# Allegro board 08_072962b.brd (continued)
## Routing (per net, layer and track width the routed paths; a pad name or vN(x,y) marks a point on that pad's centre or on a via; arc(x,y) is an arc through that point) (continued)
UNNAMED_2_ADLTM4638_I41_PGOOD: length 3.9
  TOP w0.203: U2.B5 v3(53.09,54.2)
  BOTTOM w0.203: R51.1 55.21,54.74 53.63,54.74 v3(53.09,54.2)
UNNAMED_2_ADLTM4638_I41_PHMODE: length 5.3
  TOP w0.203: U2.G5 v3(53.09,49.4)
  BOTTOM w0.203: R7.2 R12.1 55.52,48.67 55.32,48.87 53.62,48.87 v3(53.09,49.4)
UNNAMED_2_ADLTM4638_I41_RUN: length 5.8
  TOP w0.203: U2.B4 v3(52.29,54.2)
  BOTTOM w0.203: R15.2 R9.2 53.34,55.25 v3(52.29,54.2)
UNNAMED_2_ADLTM4638_I41_TRACK: length 6.2
  TOP w0.203: U2.E2 v3(50.69,51.8)
  L4_SIG w0.152: v3(50.69,51.8) 50.69,49.97 51.1,49.57 51.1,49.01 50.23,48.14 49.69,48.14 v1(49.66,48.12)
  BOTTOM w0.203: R20.1 49.63,48.14 v1(49.66,48.12)
UNNAMED_2_ADLTM4638_I41_TSENSE: length 2.2
  TOP w0.203: U2.A6 v3(53.89,54.2)
  BOTTOM w0.406: R19.2 53.89,52.75 v3(53.89,54.2)
UNNAMED_2_ADLTM4638_I61_COMPA: length 4.4
  TOP w0.203: U3.D1 v3(62.96,51.8)
  BOTTOM w0.203: R31.2 59.39,52.05 C25.2 61.66,52.05 R40.1 62.11,51.8 v3(62.96,51.8)
UNNAMED_2_ADLTM4638_I61_COMPB: length 1.9
  TOP w0.203: U3.F1 v3(62.96,51)
  BOTTOM w0.203: v3(62.96,51) 62.11,51 R40.2
UNNAMED_2_ADLTM4638_I61_FREQ: length 5.9
  TOP w0.203: U3.E1 v3(63.76,51)
  L4_SIG w0.152: v1(61.44,48.88) 61.8,49.24 61.8,49.24 62.06,49.5 62.06,49.91 62.34,50.2 62.96,50.2 v3(63.76,51)
  BOTTOM w0.203: R25.1 R24.2 v1(61.44,48.88)
UNNAMED_2_ADLTM4638_I61_PGOOD: length 3.9
  TOP w0.203: U3.B5 v3(66.96,54.2)
  BOTTOM w0.203: v3(66.96,54.2) 67.5,54.74 69.08,54.74 R52.1
UNNAMED_2_ADLTM4638_I61_PHMODE: length 5.3
  TOP w0.203: U3.G5 v3(66.96,49.4)
  BOTTOM w0.203: R28.2 R34.1 69.39,48.67 69.19,48.87 67.49,48.87 v3(66.96,49.4)
UNNAMED_2_ADLTM4638_I61_RUN: length 5.8
  TOP w0.203: U3.B4 v3(66.16,54.2)
  BOTTOM w0.203: R38.2 R30.2 67.21,55.25 v3(66.16,54.2)
UNNAMED_2_ADLTM4638_I61_TRACK: length 6.2
  TOP w0.203: U3.E2 v3(64.56,51.8)
  L4_SIG w0.152: v3(64.56,51.8) 64.56,49.97 64.97,49.57 64.97,49.01 64.1,48.14 63.55,48.14 v1(63.52,48.12)
  BOTTOM w0.203: R44.1 63.49,48.14 v1(63.52,48.12)
UNNAMED_2_ADLTM4638_I61_TSENSE: length 2.2
  TOP w0.203: U3.A6 v3(67.76,54.2)
  BOTTOM w0.406: v3(67.76,54.2) 67.76,52.75 R41.2
UNNAMED_2_ADLTM4638_I71_COMPA: length 4.4
  TOP w0.203: U4.D1 v3(76.83,51.8)
  BOTTOM w0.203: v3(76.83,51.8) 75.98,51.8 R42.1 75.53,52.05 C26.2 73.26,52.05 R33.2
UNNAMED_2_ADLTM4638_I71_COMPB: length 1.9
  TOP w0.203: U4.F1 v3(76.83,51)
  BOTTOM w0.203: v3(76.83,51) 75.98,51 R42.2
UNNAMED_2_ADLTM4638_I71_FREQ: length 5.9
  TOP w0.203: U4.E1 v3(77.63,51)
  L4_SIG w0.152: v1(75.31,48.88) 75.67,49.24 75.67,49.24 75.93,49.5 75.93,49.91 76.21,50.2 76.83,50.2 v3(77.63,51)
  BOTTOM w0.203: R27.1 R26.2 v1(75.31,48.88)
UNNAMED_2_ADLTM4638_I71_PGOOD: length 3.9
  TOP w0.203: U4.B5 v3(80.83,54.2)
  BOTTOM w0.203: R53.1 82.95,54.74 81.37,54.74 v3(80.83,54.2)
UNNAMED_2_ADLTM4638_I71_PHMODE: length 5.3
  TOP w0.203: U4.G5 v3(80.83,49.4)
  BOTTOM w0.203: v3(80.83,49.4) 81.36,48.87 83.06,48.87 83.26,48.67 R36.1 R29.2
UNNAMED_2_ADLTM4638_I71_RUN: length 5.8
  TOP w0.203: U4.B4 v3(80.03,54.2)
  BOTTOM w0.203: R39.2 R32.2 81.08,55.25 v3(80.03,54.2)
UNNAMED_2_ADLTM4638_I71_TRACK: length 6.2
  TOP w0.203: U4.E2 v3(78.43,51.8)
  L4_SIG w0.152: v1(77.4,48.12) 77.42,48.14 77.97,48.14 78.84,49.01 78.84,49.57 78.43,49.97 v3(78.43,51.8)
  BOTTOM w0.203: R45.1 77.37,48.14 v1(77.4,48.12)
UNNAMED_2_ADLTM4638_I71_TSENSE: length 2.2
  TOP w0.203: U4.A6 v3(81.63,54.2)
  BOTTOM w0.406: R43.2 81.63,52.75 v3(81.63,54.2)
UNNAMED_2_CAP_I324_N2: length 1.1
  BOTTOM w0.203: R3.1 31.62,49.67 C2.2
UNNAMED_3_ADLTC6902_I54_SET: length 1.5
  TOP w0.203: R59.2 U6.10
UNNAMED_3_CAP_I44_N1: length 5.6
  BOTTOM w1.219: 34.8,19.38 34.8,21.11 C47.1 ; 34.8,19.38 L2.1 ; 34.8,19.38 L1.2
UNNAMED_3_CN3P_I18_N1: length 2.4
  BOTTOM w0.203: R48.2 P5.1
UNNAMED_3_LINLT3088_I55_OUT1: length 1.3
  TOP w0.203: U5.2 R60.1
UNNAMED_3_LINLT3088_I55_SET: length 1.3
  TOP w0.203: R58.1 U5.4
V+: length 76.7
  TOP w0.203: R65.1 v2(64.7,30.67) ; R59.1 v1(58.16,29.87) ; R61.1 v2(64.7,31.87) ; R63.1 v1(55.57,29.12)
  TOP w0.406: v1(58.9,27.62) 58.33,27.62 R60.2
  L4_SIG w0.457: v2(64.7,31.87) 67.34,31.87 71,28.22 116.69,28.22 117.29,27.62 TP29.1 ; v1(58.9,27.62) 56.1,27.62 55.57,28.16 v1(55.57,29.12) 56.31,29.87 v1(58.16,29.87) 63.9,29.87 v2(64.7,30.67)
  L4_SIG w0.508: v2(64.7,31.87) v2(64.7,30.67)
VOSNS+: length 63.3
  TOP w0.203: U1.B1 v3(35.22,54.2)
  L3_SIG w0.152: v3(35.22,54.2) 32.6,54.2 31.3,55.49 31.3,71.37 49.06,89.12 56.47,89.12 v1(57.43,90.09) 57.43,92 54.13,95.3 TP12.1
  BOTTOM w0.203: R46.1 v1(57.43,90.09)
VOSNS-: length 111
  TOP w0.203: U2.C2 v3(49.89,53.4) ; U1.C2 v3(36.03,53.4) ; U3.C2 v3(63.76,53.4) ; U4.C2 v3(77.63,53.4)
  L3_SIG w0.152: v3(49.89,53.4) 49.89,55.8 ; 49.89,55.8 37.15,55.8 36.03,54.68 ; 49.89,55.8 63.76,55.8 ; 36.03,54.68 v3(36.03,53.4) ; 36.03,54.68 32.84,54.68 v1(31.94,55.58) 31.81,55.71 31.81,71.37 49.21,88.77 58.93,88.77 v2(60.23,90.06) ; v3(63.76,53.4) 63.76,55.8 ; 63.76,55.8 75.91,55.8 77.63,54.08 v3(77.63,53.4)
  BOTTOM w0.203: R47.1 v2(60.23,90.06) ; C23.2 32.72,55.53 R22.2 v1(31.94,55.58)
VOUT: length 144.4
  TOP w0.203: TP13.1 55.38,91.69 ; TP13.1 54.13,90.44 ; TP13.1 52.89,91.69 ; TP13.1 54.13,92.93
  TOP w0.406: U4.F3 U4.G3 v3(78.43,49.4) ; v3(64.56,49.4) U3.G3 U3.F3 ; v3(50.69,49.4) U2.G3 U2.F3 ; U1.G3 v3(36.82,49.4)
  L4_SIG w0.152: v1(32.67,58.85) 32.67,71.18 51.26,89.76 55.24,89.76 57.43,91.95 v1(57.43,94.11) ; v1(58.13,96.09) 58.64,95.58 61.34,95.58 61.5,95.43 61.5,92.71 65.69,88.52 101.07,88.52 106.91,94.36 J3.1
  L5_PWR w0.203: 54.13,90.44 TP13.1 ; TP13.1 54.13,92.93 ; TP13.1 52.89,91.69 ; TP13.1 55.38,91.69
  BOTTOM w0.203: 54.13,90.44 TP13.1 ; TP13.1 54.13,92.93 ; TP13.1 55.38,91.69 ; TP13.1 52.89,91.69 ; v1(57.43,94.11) 57.43,95.36 ; v1(57.43,94.11) R46.2 ; v1(57.43,94.11) 58.49,94.11 ; v1(57.43,94.11) 56.38,94.11 ; R46.2 58.13,92.32 ; R46.2 57.43,91.76 ; R46.2 56.73,92.32 ; 57.49,96.09 v1(58.13,96.09) ; v1(58.13,96.09) 58.13,96.79 ; v1(58.13,96.09) 58.77,96.09 ; v1(58.13,96.09) 58.13,95.39
  BOTTOM w0.457: C77.1 J3.1 ; J3.1 C78.1 ; J3.1 C57.1 ; C22.1 32.67,56.83 R67.1 v1(32.67,58.85)
  vias: v1(36.6,64.68) v1(36.6,64.02) v1(36.6,63.36) v1(36.6,61.92) v1(36.6,61.26) v1(36.6,60.6) v1(36.6,59.15) v1(36.6,58.49) v1(36.6,57.83) v1(37.26,57.05) v1(37.26,56.6) v1(50.47,64.68) v1(50.47,64.02) v1(50.47,63.36) v1(50.47,61.92) v1(50.47,61.26) v1(50.47,60.6) v1(50.47,59.15) v1(50.47,58.49) v1(50.47,57.83) v1(51.13,57.05) v1(51.13,56.6) v1(64.34,64.68) v1(64.34,64.02) v1(64.34,63.36) v1(64.34,61.92) v1(64.34,61.26) v1(64.34,60.6) v1(64.34,59.15) v1(64.34,58.49) v1(64.34,57.83) v1(65,57.05) v1(65,56.6) v1(78.21,64.68) v1(78.21,64.02) v1(78.21,63.36) v1(78.21,61.92) v1(78.21,61.26) v1(78.21,60.6) v1(78.21,59.15) v1(78.21,58.49) v1(78.21,57.83) v1(78.87,57.05) v1(78.87,56.6) v1(96.05,76.88) v2(37.12,66.3) v2(37.12,65.59) v2(37.83,66.3) v2(37.83,65.59) v2(38.54,66.3) v2(38.54,65.59) v2(50.99,66.3) v2(50.99,65.59) v2(51.7,66.3) v2(51.7,65.59) v2(52.41,66.3) v2(52.41,65.59) v2(64.86,66.3) v2(64.86,65.59) v2(65.57,66.3) v2(65.57,65.59) v2(66.28,66.3) v2(66.28,65.59) v2(78.73,66.3) v2(78.73,65.59) v2(79.44,66.3) v2(79.44,65.59) v2(80.15,66.3) v2(80.15,65.59) v3(35.06,49.8) v3(35.06,49.35) v3(36.03,49.4) v3(49.09,49.4) v3(49.89,49.4) v3(62.96,49.4) v3(63.76,49.4) v3(76.83,49.4) v3(77.63,49.4)

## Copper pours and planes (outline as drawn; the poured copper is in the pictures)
GND on TOP: 44.96,48.34 44.96,69.32 39.3,69.32 39.3,54 36.22,54 36.22,52.79 38.62,52.79 38.62,48.34
GND on TOP: 86.57,48.86 86.57,69.32 80.91,69.32 80.91,54 77.83,54 77.83,52.79 80.23,52.79 80.23,48.86
GND on TOP: 58.83,48.34 58.83,69.32 53.17,69.32 53.17,54 50.09,54 50.09,52.79 52.49,52.79 52.49,48.34
GND on TOP: 1.32,104.17 124.64,104.17 124.64,1.27 1.27,1.27 ; 1 cut-out
GND on TOP: 72.7,48.34 72.7,69.32 67.04,69.32 67.04,54 63.96,54 63.96,52.79 66.36,52.79 66.36,48.34
GND on BOTTOM: 86.57,48.94 86.57,69.32 80.91,69.32 80.91,54 78.87,54 78.87,52.79 80.23,52.79 80.23,48.94
GND on BOTTOM: 44.96,48.94 44.96,69.32 39.3,69.32 39.3,54 37.21,54 37.21,52.79 38.62,52.79 38.62,48.94
GND on BOTTOM: 1.32,104.17 124.64,104.17 124.64,1.27 1.27,1.27 ; 19 cut-outs
GND on BOTTOM: 72.7,48.94 72.7,69.32 67.04,69.32 67.04,54 64.98,54 64.98,52.79 66.36,52.79 66.36,48.94
GND on BOTTOM: 58.83,48.94 58.83,69.32 53.17,69.32 53.17,54 51.11,54 51.11,52.79 52.49,52.79 52.49,48.94
GND on L2_GND: 1.27,1.27 1.32,104.17 124.64,104.17 124.64,1.27
GND on L3_SIG: 1.27,1.27 1.32,104.17 124.64,104.17 124.64,1.27 ; 4 cut-outs
GND on L4_SIG: 1.27,1.27 1.32,104.17 124.64,104.17 124.64,1.27 ; 2 cut-outs
GND on L5_PWR: 1.27,1.27 1.32,104.17 124.64,104.17 124.64,1.27 ; 4 cut-outs
VIN on BOTTOM (solid shape): 38.63,45.84 38.63,39.31 35.51,39.31 35.51,45.03 36.92,46.44 38.04,46.44
VIN on BOTTOM (solid shape): 52.5,45.78 52.5,39.31 49.38,39.31 49.38,45.03 50.79,46.44 51.84,46.44
VIN on BOTTOM (solid shape): 66.37,45.78 66.37,39.31 63.25,39.31 63.25,45.03 64.65,46.44 65.71,46.44
VIN on BOTTOM (solid shape): 80.24,45.78 80.24,39.31 77.12,39.31 77.12,45.04 78.52,46.44 79.58,46.44
VIN on TOP: 37.02,51.19 37.02,52.4 38.36,52.4 38.36,49.12 38.58,48.89 38.58,44.62 38.02,44.05 35.51,44.05 35.51,48.86 37.49,48.86 37.75,49.12 37.75,51.19
VIN on TOP: 64.76,51.19 64.76,52.4 66.1,52.4 66.1,49.12 66.32,48.89 66.32,44.62 65.76,44.05 63.25,44.05 63.25,48.86 65.22,48.86 65.48,49.12 65.48,51.19
VIN on TOP: 78.63,51.19 78.63,52.4 79.97,52.4 79.97,49.12 80.19,48.89 80.19,44.62 79.63,44.05 77.12,44.05 77.12,48.86 79.09,48.86 79.35,49.12 79.35,51.19
VIN on TOP: 50.89,51.19 50.89,52.4 52.23,52.4 52.23,49.12 52.45,48.89 52.45,44.62 51.89,44.05 49.38,44.05 49.38,48.86 51.35,48.86 51.62,49.12 51.62,51.19
VIN on TOP: 58.7,21.84 58.7,4.39 33.99,4.39 33.99,13.56 51.51,13.56 51.51,21.81 54.9,21.81 56.52,23.43 56.52,23.89 57.3,23.89 57.3,23.25
VIN on BOTTOM: 35.51,48.24 35.51,45.03 37.97,45.03 37.97,48.24
VIN on BOTTOM: 57.24,21.08 57.24,4.39 33.99,4.39 33.99,17.81 39.07,17.81 39.07,13.56 51.52,13.56 51.52,21.08
VIN on BOTTOM: 63.25,48.24 63.25,45.03 65.71,45.03 65.71,48.24
VIN on BOTTOM: 49.38,48.24 49.38,45.03 51.84,45.03 51.84,48.24
VIN on BOTTOM: 77.12,48.24 77.12,45.04 79.58,45.04 79.58,48.24
VIN on L5_PWR: 80.19,47.88 80.19,21.84 58.7,21.84 58.7,4.39 33.99,4.39 33.99,13.61 40.87,13.61 40.87,21.81 35.39,21.81 35.39,47.88
VIN on L5_PWR: 65.16,52.45 65.16,47.57 66.4,47.57 66.4,52.45
VIN on L5_PWR: 37.42,52.45 37.42,47.57 38.66,47.57 38.66,52.45
VIN on L5_PWR: 79.03,52.45 79.03,47.57 80.19,47.57 80.19,52.45
VIN on L5_PWR: 51.29,52.48 51.29,47.55 52.53,47.55 52.53,52.48
VINEMI on BOTTOM: 33.48,17.81 33.48,4.39 13.01,4.39 13.01,19.41 28.02,19.41 28.02,17.81
(no net) on TOP: 56,30.68 56,29.79 56.35,29.44 56.35,28.55 56.96,28.55 56.96,29.44 57.32,29.79 57.32,30.68
(no net) on TOP: 61,30.68 61,27.35 57.85,27.35 57.85,30.68
(no net) on TOP: 56.02,27.01 56.02,24.23 57.3,24.23 57.3,27.01 56.96,27.35 56.96,28.24 56.35,28.24 56.35,27.35
(no net) on BOTTOM: 77.12,45.04 77.12,39.31 80.24,39.31 80.24,45.78 79.58,46.44 78.52,46.44
(no net) on BOTTOM: 35.51,45.03 35.51,39.31 38.63,39.31 38.63,45.84 38.04,46.44 36.92,46.44
(no net) on BOTTOM: 49.38,45.03 49.38,39.31 52.5,39.31 52.5,45.78 51.84,46.44 50.79,46.44
(no net) on BOTTOM: 63.25,45.03 63.25,39.31 66.37,39.31 66.37,45.78 65.71,46.44 64.65,46.44
UNNAMED_3_ADLTC6902_I54_SET on TOP (solid shape): 57.32,29.79 56.96,29.44 56.96,28.55 56.35,28.55 56.35,29.44 56,29.79 56,30.67 57.32,30.67
UNNAMED_3_LINLT3088_I55_OUT1 on TOP (solid shape): 56.96,27.35 57.3,27.01 57.3,24.23 57.11,24.23 56.71,24.23 56.61,24.23 56.21,24.23 56.02,24.23 56.02,27.01 56.35,27.35 56.35,28.24 56.96,28.24
V+ on TOP (solid shape): 60.34,30.67 61,30.67 61,27.35 57.85,27.35 57.85,30.68 60.28,30.68
VOUT on TOP: 32.16,102.36 32.16,49.12 97.31,49.12 97.31,102.36
VOUT on BOTTOM: 32.17,54.39 32.17,102.36 97.31,102.36 97.31,54.39 ; 2 cut-outs
VOUT on L5_PWR: 32.16,102.36 58.58,102.36 58.58,70.48 58.61,70.4 58.7,70.36 80.64,70.36 80.64,54.39 77.44,54.39 77.44,49.79 78.64,49.79 78.64,49.14 74.13,49.14 74.13,54.39 63.57,54.39 63.57,49.79 64.77,49.79 64.77,49.14 60.26,49.14 60.26,54.39 49.7,54.39 49.7,49.79 50.9,49.79 50.9,49.14 46.39,49.14 46.39,54.39 35.83,54.39 35.83,49.79 37.03,49.79 37.03,49.14 32.16,49.14

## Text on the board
Ref Des/Assembly Bottom: -
Ref Des/Silkscreen Bottom: 08-072962 REV B | CLK1 | SW1 | CLK2 | VOUT | VOSNS | SW2 | CLK3 | SW3 | CLK4 | SW4 | + | -
User.Comments: (4 PLACES) | SEE NOTE 7 | 8.    SEE "DETAIL C" TO INSTALL  KFH-032-10ET. | 5.    BOARDS TO BE SHIPPED SINGULATED AFTER ASSEMBLY PROCESS. | SMOOTHEN EDGES AND FREE FROM BURS AFTER DEPANELIZATION PROCESS. | 6.    INSTALL JUMPER SHUNT(M033288) ON POSITIONS 1 AND 2 OF P5. | 7.    INSTALL STANDOFFS(M038858) TO BE MOUNTED ON SECONDARY SIDE. | > P3 & P4 | SEE DETAIL A | (3 PLACES) | SEE DETAIL B | (2 PLACES) | SEE NOTE 8 | (11 PLACES) | MFG_PN: 4705 | NOT TO SCALE | DETAIL C | MFG_PN: KFH-032-10ET | MFG_PN: 4703 | (CONN TERM LUG LOCKWASHER #10 FLAT) | (...UNINSULATED); OPTIONAL | MFG_PN: 913
Ref Des/Silkscreen Top: PGOOD | RUN | TRACK/SS | ON | OFF | VIN EMI | VOUT | VIN | VOSNS+ | 3.1V - 20V | GND | V | IO STEP CLK | EVAL-LTM4638-AZ | + | LTM4638EV | HIGH DENSITY POLYPHASE | STEP-DOWN POWER uMODULE REGULATOR | IOSTEP CLK | IOSTEP | FOR CUSTOMER USE ONLY
PAGE_OUTLINE: A1 | B | AS PER ECR-117589 | AS PER ECR-120151 | 23OCT23 | 03MAY24 | R. SUMAWAN III | J. DELOSSANTOS | CUSTOMER EVALUATION Z
BODY_CENTER: FAB NOTES REVISION: 2ND NOVEMBER 2022 | 8.   IMPEDANCE REQUIREMENTS: IF NO STACKUP IS DEFINED, THE VENDOR IS ALLOWED TO ADJUST THE DIELECTRIC | 13.  PLATING SPECIFICATION: | 9.   FILLET OPTIONS TO ENHANCE RELIABILITY AT PAD JUNCTIONS WHERE SPACING PERMITS. | 10.  THIEVING: | 11.  LAYER TO LAYER REGISTRATION SHALL BE WITHIN 0.003 INCHES. | 12.  DRILL SIZES ARE FINISHED HOLE SIZES. ALL HOLES SHALL BE LOCATED WITHIN 0.005 INCHES DTP,UNLESS SPECIFIED. | 14.  SURFACE FINISH: | 15.  SOLDERMASK: | 1.   DIMENSIONS ARE IN INCHES (EXCEPT WHERE NOTED). | ALL DOCUMENTS & SPECIFICATIONS REFERRED TO BELOW SHOULD BE THE LATEST REVISIONS. | 2.  BOARD MATERIAL:(USE CHECKED ITEMS) | 3.   ALL LAMINATES & BONDING MATERIALS SHOULD BE SELECTED FROM IPC-4101 OR IPC-4103,(TG>170 DEGC TD>300 DEGC) | 4.   REFER TO IPC-6010 SERIES, CLASS 2 FOR FABRICATION. | 5.   REFER TO LAMINATION DIAGRAM FOR OVERALL BOARD THICKNESS, TOLERANCE APPLIES AFTER ALL LAMINATION AND PLATING | 6.   BOW & TWIST NOT TO EXCEED 0.0075 INCHES (0.75%) PER LINEAR INCH AND SHOULD BE MEASURED PER IPC-TM-650, METHOD 2.4.22. | 7.   ACCEPTABILITY PER ADI SPECIFICATION TST00115. | 16.  APPLY SILKSCREEN TO BOTH SIDES USING A NON-CONDUCTIVE, EPOXY BASED INK PER ARTWORK. | HOMOGENOUS MATERIALS IN THIS BOARD SHALL BE COMPLAINT WITH THE EU DIRECTIVE 2002/95/EC | ( ) FILLETS ALLOWED | (X) FILLETS NOT ALLOWED | ( ) VENDOR MAY ADD THIEVING TO COMPENSATE FOR LOW COPPER DENSITY AREAS MAINTAINING A MINIMUM | (X) VENDOR MAY NOT ADD THIEVING TO COMPENSATE FOR LOW COPPER DENSITY AREAS. | (X) LPI | ( ) OTHER_________ | COLOR | (X) GREEN | (X) WHITE | ( ) OTHER | HINDER PROPER SOLDER WICKING. BARREL RELIEF ON SOLDERMASK ALLOWED IN UNFILLED VIA IN PAD HOLES. | (X) REFER TO LAMINATION DIAGRAM FOR FINISHED COPPER WEIGHT/THICKNESS REQUIRMENTS | (X) IMMERSION GOLD (ENIG) 1.58-3.94 MICRO INCHES OVER 118-236 MICRO INCHES MIN. OF ELECTROLESS NICKEL PER IPC-4552 | ( ) OSP (ORGANIC SOLDERABILITY PRESERVATIVE) | ( ) IMMERSION SILVER | ( ) SOFT WIRE BONDABLE GOLD 30-50 MICRO INCHES OF SOFT WIRE | ( ) EDGE CONNECTOR FINGERS ARE TO BE PLATED WITH 100 MICRO-INCHES(.0001") OF LOW STRESS | THICKNESS & TRACE WIDTHS TO MEET THE IMPEDANCE REQUIREMENT. IF SPECIFIED, THE VENDOR MUST | TRACE WIDTH & SPACING THAT IMPACT THE REQUIREMENTS MUST HAVE WRITTEN APPROVAL FROM ADI. | MINIMUM BARREL PLATING OF 0.001 INCHES. PLATED HOLES SHALL NOT BE ROUGH OR IRREGULAR SO AS TO | SOLDERMASK OVER BARE COPPER OR BARE GOLD (BOTH SIDES) TO MEET IPC-SM-840. | IF PRESENT,DO NOT MODIFY SOLDERMASK DEFINED PADS (MASK OPENINGS LESS THAN COPPER PAD) WITHOUT APPROVAL. | MEET THE REQUIREMENTS LISTED IN THE IMPEDANCE TABLE. ANY ADJUSTMENT MADE TO THE DEFINED STACKUP, | PROCESSES. FINISHED THICKNESS MEASURED FROM TOP COPPER TO BOTTOM COPPER. | (X)  ISOLA370HR OR S1000-2 OR IT180 OR EQUIVALENT | ( )  ISOLA-FR408HR OR EQUIVALENT | ( )  ISOLA IS410 | ( )  MEGTRON 6 | ( )  NELCO-4000-13 | ( )  ROGERS 4350B | ( ) ROGERS 3003 | ( ) ARLON 85N | ( ) EM370D | ( )  OTHER ________________________ | UL FLAMMABILITY RATING 94V-0. BOARD MATERIAL & CONSTRUCTION SHALL MEET THE REQUIREMENTS OF UL796/UL796F. | BONDABLE GOLD OVER 100-150 MICRO INCHES OF NICKEL | NICKEL UNDER 30 MICRO-INCHES (.0003') OF GOLD | 0.100 INCH CLEARANCE FROM ALL COPPER FEATURES, | THE STARTING COPPER WEIGHT/THICKNESS CAN VARY AS LONG AS THE FINISHED COPPER | WEIGHT/THICKNESS IS NOT LESS THAN THE SPECIFIED VALUE. | UNLESS OTHERWISE SPECIFIED | WORKMANSHIP SHALL CONFORM TO IPC-A-600, CLASS 2. | 21.  INTENTIONAL SHORTS: | 17.  FINAL ELECTRICAL TEST TO BE PERFORMED USING PROVIDED IPC-D-356A NETLIST OR ODB++ FORMAT FILE. | 22.  PEMNUTS: | 23.  MANUFACTURER TO ETCH/STAMP WITH PERMANENT NON-CONDUCTIVE INK | ON SECONDARY SIDE UNLESS OTHERWISE SPECIFIED: | 18.  A TIME DOMAIN REFLECTOMETER REPORT (TDR) FOR EACH IMPEDANCE CONTROLLED LAYER & A CERTIFICATE | 19.  IF PRESENT, ALL BLIND/BURIED VIAS WITH AN ASPECT RATIO <1:1 TO BE PLATED SHUT WITH COPPER WHEN | 20.  FOR VIA FILL INFORMATION REFER TO DRILL CHART: | 25. PANELIZATION: | 27.  MINIMUM DESIGN LINE WIDTH IS .005 INCH. | 28.  MINIMUM DESIGN LINE SPACING IS .005 INCH. | IS ACCEPTABLE, ALL OTHER INSTANCES MUST BE REPORTED. | IF AN INTENTIONAL SHORT REPORT IS SUPPLIED AND DOES NOT MATCH THE FAB DATA THEN | THE PCB SHALL HAVE A VERIFICATION STAMP. | ( )  NON-CONDUCTIVE EPOXY FILL ALL DRILLED VIAS | ( )  COPPER FILL ALL DRILLED VIAS | ( ) PEMNUTS TO BE INSTALLED BY FABRICATOR | ( ) PEMNUTS NOT TO BE INSTALLED BY FABRICATOR | (X) NOT APPLICABLE | USED AS VIA-IN-PAD OR AS A STACKED VIA. BLIND/BURIED VIAS WITH AN ASPECT RATIO >1:1 TO BE FILLED | A. UL CODE-FLAMMABILITY RATING FOR THOSE APPROVED MATERIALS(IF APPLICABLE) | B. DATE CODE | C. LOT NUMBER | D. MANUFACTURER LOGO | BOARDS TO BE SHIPPED IN ARRAY AND KEPT INTACT | PANEL TO BE SUBJECTED TO CUSTOMERS APPROVAL | PANEL SOLDER PASTE STENCIL GERBER TO BE PROVIDED TO ANALOG | CAN'T BE PERFORMED BECAUSE THE TRACE LENGTH IS TOO SHORT ON THE OUTER LAYERS AT THE PIN ESCAPES | ADI APPROVAL IS REQUIRED. | OF COMPLIANCE SHALL BE PROVIDED BY VENDOR AT TIME OF SHIPMENT. INSTANCES WHERE TDR TESTING | WITH NON-CONDUCTIVE EPOXY. | TOOLING: | FINISH: | NOTES: | MATERIAL: | TESTING: | MISCELLANEOUS: | NOTE: ALL IMPEDANCE TOLERANCE +/-10% | LAYER | L1 | SE = SINGLE ENDED, DP = DIFFERENTIAL PAIR | 50 OHMS SE | IMPEDANCE | REFERENCE | L2 | LINE WIDTH | 4MILS | SPACE | N/A | IMPEDANCE TABLE
DIMENSION: - | " " | (REF) | DIA MAX
User.17: L2 GND | 08-      -07
User.18: L3 SIG | 08-      -08
User.19: L4 SIG | 08-      -09
User.20: L5 PWR | 08-      -10
User.24: L2 GND | 08-      -075
User.25: L3 GND | 08-      -085
User.26: L4 GND | 08-      -095
User.27: L5 PWR | 08-      -105
User.45: FIGURE | SIZE | 8.0 | 10.0 | 35.0 | 40.0 | 50.0 | 60.0 | 100.0 | 194.0 | 213.0 | 187.0 | DRILL CHART: TOP to BOTTOM | FINISHED HOLES IN MILS | PLATED | NON-PLATED | QTY | 883 | 138 | 2 | 3 | 12 | 4 | TOLERANCE/NOTES | SEE DETAIL B
